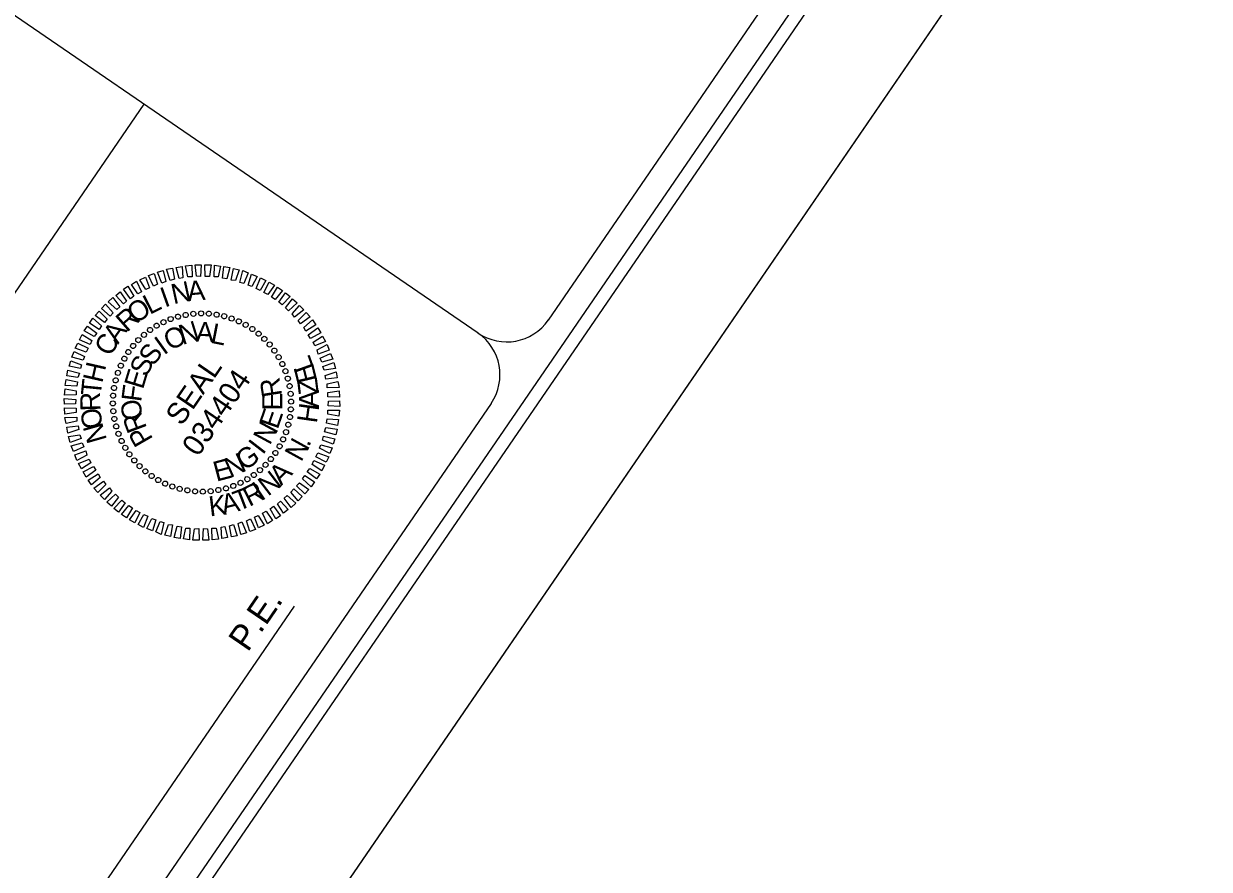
# Model space of a CAD drawing. Extents: x 2312641 to 2338852, y 590461 to 618614.
# Drawn here: x 2335572 to 2338852, y 606464 to 608804 of the extents above; entities that cross this region are included whole.
import ezdxf

# ---------------------------------------------------------------- set-up
doc = ezdxf.new("R2010")
doc.units = 0
for name, color, linetype in [('Exist Other Culture Sign Post Text', 7, 'Continuous'), ('Exist Property Iron Pin Cogo Number', 7, 'Continuous'), ('Exist Utilities Power Joint Use Telephone CELL', 7, 'Continuous'), ('Exist Utilities Power Joint Use Telephone Text', 7, 'Continuous'), ('Exist Vegetation Woods Line Text', 7, 'Continuous')]:
    doc.layers.add(name, color=color, linetype=linetype)

msp = doc.modelspace()

# ---------------------------------------------------------------- linework, layer by layer
at = {"layer": 'Exist Other Culture Sign Post Text'}
msp.add_line((2325524.4, 590461.2), (2338852.2, 609908.5), dxfattribs=at)
at = {"layer": 'Exist Property Iron Pin Cogo Number'}
for p, q in [((2336829.3, 607947.5), (2334981.6, 609213.7)), ((2334158.7, 606032.4), (2335905.2, 608580.8)), ((2335201.2, 605558.1), (2336321.2, 607192.1))]:
    msp.add_line(p, q, dxfattribs=at)
for points in [[(2326636.7, 592703), (2338350, 609794.5)], [(2337024, 607983.8), (2338252.5, 609776.4)], [(2335284.6, 605445.8), (2336865.7, 607752.9)]]:
    msp.add_lwpolyline(points, dxfattribs=at)
for centre, start, end in [((2336907.9, 608063.4), 235.5761, 325.5761), ((2336749.6, 607832.5), 325.5761, 55.5761)]:
    msp.add_arc(centre, 140, start, end, dxfattribs=at)
at = {"layer": 'Exist Utilities Power Joint Use Telephone CELL'}
msp.add_lwpolyline([(2326149.2, 618614.2), (2312821.5, 599166.9), (2325524.4, 590461.2), (2338852.2, 609908.5)], close=True, dxfattribs=at)
at = {"layer": 'Exist Utilities Power Joint Use Telephone Text'}
msp.add_lwpolyline([(2325368.2, 590788.9), (2338557.5, 610034.1), (2326372.9, 618384.6), (2313183.6, 599139.4)], close=True, dxfattribs=at)
at = {"layer": 'Exist Vegetation Woods Line Text'}
for p, q in [((2336041.2, 608001.7), (2336041.2, 608001.7)), ((2336062.4, 608002.5), (2336062.4, 608002.5)), ((2336084.2, 608001.6), (2336084.2, 608001.6)), ((2335939.5, 607968.1), (2335939.5, 607968.1)), ((2335958.3, 607978.7), (2335958.3, 607978.7)), ((2335978.3, 607986.7), (2335978.3, 607986.7)), ((2335998.9, 607993.7), (2335998.9, 607993.7)), ((2336019.6, 607998.3), (2336019.6, 607998.3)), ((2336105.6, 607999.3), (2336105.6, 607999.3)), ((2336126.3, 607995), (2336126.3, 607995)), ((2336146.8, 607988.5), (2336146.8, 607988.5)), ((2336167, 607979.9), (2336167, 607979.9)), ((2336186.3, 607970.7), (2336186.3, 607970.7)), ((2335904.2, 607943.1), (2335904.2, 607943.1)), ((2335921.3, 607956.5), (2335921.3, 607956.5)), ((2336204.6, 607959.2), (2336204.6, 607959.2)), ((2336221.9, 607946.1), (2336221.9, 607946.1)), ((2335874.6, 607912.5), (2335874.6, 607912.5)), ((2335889.1, 607928.3), (2335889.1, 607928.3)), ((2336237.6, 607931.6), (2336237.6, 607931.6)), ((2336252.4, 607916.5), (2336252.4, 607916.5)), ((2335849.9, 607877), (2335849.9, 607877)), ((2335861.5, 607895.3), (2335861.5, 607895.3)), ((2336265.9, 607899.4), (2336265.9, 607899.4)), ((2336277.4, 607881.1), (2336277.4, 607881.1)), ((2335832.1, 607837.5), (2335832.1, 607837.5)), ((2335840.8, 607857.7), (2335840.8, 607857.7)), ((2336288, 607862.4), (2336288, 607862.4)), ((2336296, 607842.4), (2336296, 607842.4)), ((2335825.7, 607817), (2335825.7, 607817)), ((2336303, 607821.8), (2336303, 607821.8)), ((2335819.1, 607774.8), (2335819.1, 607774.8)), ((2335821.4, 607796.3), (2335821.4, 607796.3)), ((2336307.6, 607801.1), (2336307.6, 607801.1)), ((2336311, 607779.4), (2336311, 607779.4)), ((2335818.2, 607753), (2335818.2, 607753)), ((2336311.8, 607758.3), (2336311.8, 607758.3)), ((2335819, 607731.9), (2335819, 607731.9)), ((2335822.4, 607710.2), (2335822.4, 607710.2)), ((2336308.6, 607715.1), (2336308.6, 607715.1)), ((2336310.9, 607736.5), (2336310.9, 607736.5)), ((2335827, 607689.5), (2335827, 607689.5)), ((2336297.9, 607673.8), (2336297.9, 607673.8)), ((2336304.3, 607694.3), (2336304.3, 607694.3)), ((2335834, 607669), (2335834, 607669)), ((2335842, 607649), (2335842, 607649)), ((2336289.2, 607653.6), (2336289.2, 607653.6)), ((2335852.6, 607630.2), (2335852.6, 607630.2)), ((2335864.1, 607612), (2335864.1, 607612)), ((2336268.5, 607616), (2336268.5, 607616)), ((2336280.1, 607634.4), (2336280.1, 607634.4)), ((2335877.6, 607594.9), (2335877.6, 607594.9)), ((2335892.4, 607579.8), (2335892.4, 607579.8)), ((2336240.9, 607583), (2336240.9, 607583)), ((2336255.4, 607598.8), (2336255.4, 607598.8)), ((2335908.1, 607565.3), (2335908.1, 607565.3)), ((2335925.4, 607552.1), (2335925.4, 607552.1)), ((2335943.7, 607540.6), (2335943.7, 607540.6)), ((2336190.5, 607543.3), (2336190.5, 607543.3)), ((2336208.7, 607554.8), (2336208.7, 607554.8)), ((2336225.8, 607568.2), (2336225.8, 607568.2)), ((2335963, 607531.4), (2335963, 607531.4)), ((2335983.2, 607522.8), (2335983.2, 607522.8)), ((2336003.7, 607516.4), (2336003.7, 607516.4)), ((2336024.4, 607512.1), (2336024.4, 607512.1)), ((2336045.8, 607509.7), (2336045.8, 607509.7)), ((2336067.7, 607508.9), (2336067.7, 607508.9)), ((2336088.8, 607509.7), (2336088.8, 607509.7)), ((2336110.4, 607513), (2336110.4, 607513)), ((2336131.1, 607517.6), (2336131.1, 607517.6)), ((2336151.7, 607524.7), (2336151.7, 607524.7)), ((2336171.7, 607532.7), (2336171.7, 607532.7))]:
    msp.add_line(p, q, dxfattribs=at)
for points in [[(2336001.5, 608098.6), (2335993.9, 608129), (2336010.2, 608132.3), (2336012.1, 608100.4)], [(2336025.8, 608103.2), (2336019.7, 608134.3), (2336036.5, 608135.6), (2336037.8, 608103.5)], [(2336049.9, 608104.9), (2336045.9, 608136.4), (2336063, 608136.4), (2336060.9, 608104.7)], [(2336073.7, 608104.5), (2336072.5, 608136.5), (2336090, 608136.2), (2336085.7, 608104.8)], [(2336098.8, 608103.3), (2336099.6, 608135.7), (2336115.9, 608132.7), (2336109.9, 608103)], [(2336121.9, 608099.8), (2336125.6, 608132.2), (2336142.2, 608128.8), (2336133.6, 608098)], [(2335909.3, 608068.7), (2335893.3, 608095.2), (2335908.4, 608102.9), (2335919.4, 608073.2)], [(2335931, 608077.4), (2335916.6, 608107.5), (2335932.3, 608112.4), (2335941.9, 608083.2)], [(2335954.4, 608086.1), (2335941.8, 608116.2), (2335957.9, 608120.9), (2335965.3, 608090.1)], [(2335977.4, 608093.3), (2335967.2, 608124.2), (2335983.5, 608127.5), (2335988.7, 608097)], [(2336146.1, 608094.5), (2336151.9, 608126.6), (2336167.6, 608122.7), (2336157.4, 608092.9)], [(2336170.1, 608088), (2336178, 608120.5), (2336193.1, 608114.1), (2336180.6, 608085.2)], [(2336193, 608080), (2336202.3, 608111), (2336217.9, 608104.2), (2336203.3, 608076.7)], [(2336215.2, 608070.7), (2336227, 608101.1), (2336241.8, 608093.2), (2336226.1, 608065.8)], [(2335867.5, 608042.7), (2335847.8, 608069.2), (2335860.3, 608077.5), (2335876.6, 608050.3)], [(2335887.4, 608056.1), (2335870, 608082.3), (2335884.1, 608091.2), (2335897.9, 608062.1)], [(2336236.5, 608060.1), (2336250.8, 608089), (2336265.3, 608080.6), (2336246.9, 608054.4)], [(2336257.3, 608047), (2336273.6, 608074.5), (2336287.6, 608065.3), (2336267.1, 608040.5)], [(2335829.5, 608013), (2335805.6, 608034.7), (2335818.1, 608046.5), (2335837.3, 608020.2)], [(2335847.9, 608029.1), (2335826.5, 608052.1), (2335839, 608062.1), (2335856.4, 608035.9)], [(2336277.5, 608033), (2336295.9, 608059.2), (2336308.9, 608049.4), (2336286.8, 608025.7)], [(2336295.9, 608018), (2336315.7, 608042.6), (2336328.5, 608031.8), (2336304.4, 608009.4)], [(2335794.9, 607977.5), (2335769.4, 607996.7), (2335780.8, 608008.6), (2335803.1, 607986.3)], [(2335811.2, 607995), (2335787.4, 608016), (2335798.4, 608028.2), (2335819, 608004.1)], [(2336314.6, 608000.9), (2336334.7, 608024.2), (2336346.7, 608012.1), (2336321.1, 607991.9)], [(2336330.8, 607982.6), (2336352.9, 608004.5), (2336364.6, 607992.7), (2336337.2, 607973.6)], [(2335766.8, 607938.4), (2335738.7, 607953.9), (2335748.1, 607967.2), (2335773.7, 607947.9)], [(2335780.2, 607957.8), (2335753.5, 607975.4), (2335762.8, 607988.7), (2335787.1, 607967.4)], [(2336346.4, 607963.4), (2336370.6, 607984), (2336379.8, 607970.3), (2336352.1, 607953.2)], [(2335755.3, 607916.5), (2335726, 607929.3), (2335733.6, 607944.3), (2335760.5, 607927.2)], [(2336359.1, 607943.3), (2336385.3, 607962.5), (2336394, 607948), (2336365.4, 607933.2)], [(2336372.5, 607922.6), (2336398.2, 607939.3), (2336406.9, 607924.7), (2336377.1, 607912.6)], [(2335744.7, 607895.2), (2335714.1, 607905.9), (2335721.8, 607920.3), (2335750, 607905.8)], [(2336383.7, 607901.1), (2336411.1, 607916), (2336417.2, 607900.2), (2336386.7, 607889.7)], [(2335728.6, 607849.3), (2335697.7, 607856.1), (2335702.4, 607871.2), (2335731.4, 607859.8)], [(2335736.2, 607872.5), (2335704.7, 607880.9), (2335711.1, 607896.8), (2335739.9, 607882.5)], [(2336392, 607878), (2336420.5, 607890.9), (2336427.3, 607875.3), (2336396.2, 607867.5)], [(2335721.9, 607824.8), (2335691, 607829.9), (2335694.2, 607845.4), (2335726.2, 607836.7)], [(2336399.4, 607855.4), (2336429.5, 607866.2), (2336434.2, 607850.1), (2336403, 607844.8)], [(2336405.5, 607830.7), (2336436.2, 607840.6), (2336438.8, 607824.1), (2336407.8, 607819.9)], [(2335718.6, 607801.1), (2335686.9, 607803.1), (2335689.6, 607819.6), (2335720.8, 607812.6)], [(2336411, 607807.7), (2336440.9, 607813.9), (2336444.3, 607797.5), (2336411.6, 607796.1)], [(2335716.8, 607777), (2335684.6, 607776.4), (2335686.4, 607793.5), (2335717, 607788)], [(2336412.9, 607782.9), (2336444.2, 607787.6), (2336445.5, 607770.8), (2336413, 607771.6)], [(2335715.1, 607752.1), (2335684.2, 607750.8), (2335683.4, 607766.6), (2335716.2, 607764.4)], [(2335717.2, 607728.4), (2335685.8, 607723.8), (2335684.5, 607740.5), (2335717, 607739.7)], [(2336414.9, 607759.2), (2336445.8, 607760.6), (2336446.6, 607744.8), (2336413.8, 607746.9)], [(2335719, 607703.6), (2335689.1, 607697.5), (2335685.7, 607713.8), (2335718.4, 607715.2)], [(2336411.4, 607710.2), (2336443.1, 607708.2), (2336440.4, 607691.7), (2336409.2, 607698.8)], [(2336413.2, 607734.4), (2336445.4, 607734.9), (2336443.6, 607717.9), (2336413, 607723.3)], [(2335724.5, 607680.6), (2335693.8, 607670.8), (2335691.2, 607687.3), (2335722.2, 607691.5)], [(2336408.1, 607686.5), (2336439, 607681.5), (2336435.8, 607665.9), (2336403.8, 607674.6)], [(2335730.6, 607655.9), (2335700.5, 607645.2), (2335695.8, 607661.2), (2335727, 607666.6)], [(2335738, 607633.3), (2335709.5, 607620.4), (2335702.7, 607636), (2335733.8, 607643.8)], [(2336401.4, 607662.1), (2336432.3, 607655.2), (2336427.6, 607640.1), (2336398.6, 607651.5)], [(2335746.3, 607610.2), (2335718.9, 607595.3), (2335712.8, 607611.1), (2335743.3, 607621.6)], [(2336385.3, 607616.2), (2336415.9, 607605.4), (2336408.2, 607591), (2336380, 607605.5)], [(2336393.8, 607638.8), (2336425.3, 607630.4), (2336419, 607614.6), (2336390.1, 607628.9)], [(2335757.5, 607588.7), (2335731.8, 607572.1), (2335723.1, 607586.6), (2335752.9, 607598.8)], [(2335770.9, 607568), (2335744.7, 607548.8), (2335736.1, 607563.4), (2335764.6, 607578.1)], [(2336374.7, 607594.8), (2336404, 607582), (2336396.4, 607567), (2336369.5, 607584.2)], [(2335783.6, 607547.9), (2335759.4, 607527.4), (2335750.2, 607541.1), (2335777.9, 607558.1)], [(2336349.8, 607553.5), (2336376.5, 607535.9), (2336367.2, 607522.7), (2336342.9, 607544)], [(2336363.2, 607573), (2336391.3, 607557.4), (2336381.9, 607544.2), (2336356.3, 607563.4)], [(2335799.2, 607528.8), (2335777.1, 607506.8), (2335765.4, 607518.7), (2335792.8, 607537.7)], [(2335815.4, 607510.4), (2335795.3, 607487.2), (2335783.3, 607499.2), (2335808.9, 607519.4)], [(2336318.8, 607516.3), (2336342.6, 607495.3), (2336331.6, 607483.1), (2336311.1, 607507.3)], [(2336335.1, 607533.8), (2336360.6, 607514.6), (2336349.2, 607502.7), (2336326.9, 607525.1)], [(2335834.1, 607493.3), (2335814.4, 607468.7), (2335801.5, 607479.6), (2335825.6, 607501.9)], [(2335852.5, 607478.3), (2335834.1, 607452.2), (2335821.1, 607461.9), (2335843.2, 607485.6)], [(2336282.1, 607482.2), (2336303.5, 607459.2), (2336291, 607449.2), (2336273.6, 607475.5)], [(2336300.5, 607498.4), (2336324.4, 607476.7), (2336311.9, 607464.9), (2336292.7, 607491.1)], [(2335872.7, 607464.3), (2335856.4, 607436.9), (2335842.4, 607446.1), (2335862.9, 607470.8)], [(2335893.5, 607451.2), (2335879.2, 607422.4), (2335864.7, 607430.8), (2335883.1, 607456.9)], [(2335914.8, 607440.7), (2335903, 607410.2), (2335888.2, 607418.2), (2335903.9, 607445.5)], [(2336220.7, 607442.6), (2336236.8, 607416.1), (2336221.6, 607408.4), (2336210.6, 607438.1)], [(2336242.6, 607455.3), (2336260, 607429.1), (2336245.9, 607420.1), (2336232.1, 607449.2)], [(2336262.5, 607468.6), (2336282.2, 607442.1), (2336269.7, 607433.9), (2336253.4, 607461.1)], [(2335937, 607431.4), (2335927.7, 607400.4), (2335912.1, 607407.1), (2335926.7, 607434.6)], [(2335959.9, 607423.3), (2335952, 607390.8), (2335936.9, 607397.3), (2335949.4, 607426.1)], [(2335983.9, 607416.9), (2335978.1, 607384.8), (2335962.4, 607388.7), (2335972.6, 607418.4)], [(2336008.1, 607411.5), (2336004.4, 607379.2), (2335987.8, 607382.5), (2335996.4, 607413.4)], [(2336128.5, 607412.8), (2336136.1, 607382.4), (2336119.8, 607379), (2336117.9, 607410.9)], [(2336152.6, 607418.1), (2336162.8, 607387.1), (2336146.5, 607383.8), (2336141.3, 607414.3)], [(2336175.6, 607425.2), (2336188.2, 607395.2), (2336172.1, 607390.5), (2336164.7, 607421.2)], [(2336199, 607433.9), (2336213.4, 607403.9), (2336197.7, 607398.9), (2336188.2, 607428.2)], [(2336031.2, 607408.1), (2336030.4, 607375.6), (2336014.1, 607378.7), (2336020.1, 607408.3)], [(2336056.3, 607406.8), (2336057.5, 607374.8), (2336040, 607375.1), (2336044.3, 607406.5)], [(2336080.1, 607406.4), (2336084.1, 607374.9), (2336067, 607375), (2336069.1, 607406.6)], [(2336104.2, 607408.1), (2336110.3, 607377.1), (2336093.5, 607375.8), (2336092.3, 607407.8)]]:
    msp.add_lwpolyline(points, close=True, dxfattribs=at)
for centre, major_axis in [((2335998.8, 607993.2), (-1.9, 6.82)), ((2336019.7, 607998.1), (-1.3, 6.96)), ((2336041, 608001.1), (-0.69, 7.05)), ((2336062.5, 608002.3), (-0.07, 7.08)), ((2336084, 608001.5), (0.55, 7.06)), ((2336105.4, 607998.9), (1.16, 6.98)), ((2336126.4, 607994.5), (1.76, 6.86)), ((2335939.6, 607968), (-3.6, 6.1)), ((2335958.5, 607978.1), (-3.06, 6.39)), ((2335978.3, 607986.5), (-2.49, 6.63)), ((2336147, 607988.2), (2.35, 6.68)), ((2336167, 607980.2), (2.93, 6.45)), ((2336186.1, 607970.5), (3.48, 6.17)), ((2336204.4, 607959.1), (4, 5.84)), ((2335888.9, 607928.3), (-5.06, 4.96)), ((2335904.6, 607943), (-4.6, 5.38)), ((2335921.5, 607956.2), (-4.12, 5.76)), ((2336221.6, 607946.2), (4.5, 5.47)), ((2336237.6, 607931.8), (4.96, 5.06)), ((2335861.6, 607895.1), (-5.84, 4)), ((2335874.5, 607912.3), (-5.47, 4.5)), ((2336252.3, 607916.1), (5.38, 4.6)), ((2336265.6, 607899.1), (5.76, 4.12)), ((2335850.2, 607876.8), (-6.17, 3.48)), ((2336277.3, 607881.1), (6.1, 3.6)), ((2336287.4, 607862.1), (6.39, 3.06)), ((2335832.4, 607837.7), (-6.68, 2.35)), ((2335840.5, 607857.6), (-6.45, 2.93)), ((2336295.9, 607842.3), (6.63, 2.49)), ((2335821.7, 607796), (-6.98, 1.16)), ((2335826.2, 607817.1), (-6.86, 1.76)), ((2336302.5, 607821.9), (6.82, 1.9)), ((2336307.4, 607800.9), (6.96, 1.3)), ((2335819.1, 607774.7), (-7.06, 0.55)), ((2336310.4, 607779.6), (7.05, 0.69)), ((2335818.4, 607753.2), (-7.08, -0.07)), ((2335819.6, 607731.7), (-7.05, -0.69)), ((2336310.9, 607736.6), (7.06, -0.55)), ((2336311.6, 607758.1), (7.08, 0.07)), ((2335822.6, 607710.4), (-6.96, -1.3)), ((2336308.3, 607715.3), (6.98, -1.16)), ((2335827.5, 607689.5), (-6.82, -1.9)), ((2335834.1, 607669), (-6.63, -2.49)), ((2336297.6, 607673.7), (6.68, -2.35)), ((2336303.8, 607694.2), (6.86, -1.76)), ((2335842.6, 607649.2), (-6.39, -3.06)), ((2336279.8, 607634.5), (6.17, -3.48)), ((2336289.5, 607653.7), (6.45, -2.93)), ((2335852.7, 607630.2), (-6.1, -3.6)), ((2335864.4, 607612.2), (-5.76, -4.12)), ((2336255.5, 607599.1), (5.47, -4.5)), ((2336268.4, 607616.3), (5.84, -4)), ((2335877.7, 607595.3), (-5.38, -4.6)), ((2335892.4, 607579.6), (-4.96, -5.06)), ((2336225.4, 607568.4), (4.6, -5.38)), ((2336241.1, 607583.1), (5.06, -4.96)), ((2335908.4, 607565.2), (-4.5, -5.47)), ((2335925.6, 607552.3), (-4, -5.84)), ((2335943.9, 607540.9), (-3.48, -6.17)), ((2336171.5, 607533.2), (3.06, -6.39)), ((2336190.4, 607543.4), (3.6, -6.1)), ((2336208.5, 607555.1), (4.12, -5.76)), ((2335963, 607531.1), (-2.93, -6.45)), ((2335983, 607523.1), (-2.35, -6.68)), ((2336003.6, 607516.8), (-1.76, -6.86)), ((2336024.6, 607512.4), (-1.16, -6.98)), ((2336046, 607509.8), (-0.55, -7.06)), ((2336067.5, 607509.1), (0.07, -7.08)), ((2336089, 607510.2), (0.69, -7.05)), ((2336110.3, 607513.3), (1.3, -6.96)), ((2336131.2, 607518.1), (1.9, -6.82)), ((2336151.7, 607524.8), (2.49, -6.63))]:
    msp.add_ellipse(centre, major_axis=major_axis, ratio=0.999708, dxfattribs=at)

# ---------------------------------------------------------------- texts
at = {"layer": 'Exist Property Iron Pin Cogo Number'}
msp.add_text('P.E.', height=69.99, rotation=55.5761, dxfattribs=at).set_placement((2336191.7, 607062.8))
at = {"layer": 'Exist Vegetation Woods Line Text'}
for s, height, rotation, p in [('I', 55.4, 19.5962, (2335961.9, 608018.1)), ('N', 55.4, 12.395, (2335986.3, 608027.3)), ('A', 55.4, 5.1932, (2336026.5, 608035.6)), ('O', 55.4, 33.9972, (2335881.3, 607971.8)), ('L', 55.4, 26.797, (2335920.3, 607997.8)), ('R', 55.4, 41.1972, (2335857, 607948.3)), ('A', 55.4, 55.5964, (2335832.6, 607914.9)), ('N', 55.4, 17.0527, (2336010.8, 607914.5)), ('A', 55.4, 358.3363, (2336047.6, 607923.8)), ('L', 55.5, 348.9769, (2336086.5, 607921.2)), ('C', 55.4, 62.7959, (2335813.7, 607880.9)), ('I', 55.4, 35.7657, (2335959.7, 607885.3)), ('O', 55.4, 26.4096, (2335976.3, 607897.9)), ('S', 55.4, 54.4765, (2335930.6, 607853.8)), ('S', 55.4, 63.8317, (2335911.6, 607824)), ('L', 55.4, 109.8751, (2336375.9, 607851.2)), ('H', 55.4, 77.1956, (2335788.9, 607807.7)), ('E', 55.4, 73.1871, (2335901.5, 607790)), ('SEAL', 58.98, 55.5761, (2336008.9, 607688.5)), ('034404', 59, 55.5761, (2336054.3, 607603.2)), ('E', 55.4, 103.7004, (2336383.9, 607817.5)), ('T', 55.4, 84.3958, (2335784.9, 607772.1)), ('F', 55.4, 82.5431, (2335896.5, 607755.6)), ('R', 55.4, 99.0575, (2336287, 607775.2)), ('Z', 55.4, 97.1609, (2336388.4, 607781.2)), ('R', 55.4, 91.5966, (2335784.5, 607732.3)), ('E', 55.4, 89.7002, (2336287.1, 607733.4)), ('A', 55.4, 89.9112, (2336388.4, 607740.7)), ('O', 55.4, 98.7978, (2335791.2, 607687.2)), ('O', 55.4, 101.2573, (2335902.8, 607712.5)), ('E', 55.4, 70.9878, (2336274.4, 607679.3)), ('H', 55.4, 81.9512, (2336382.6, 607696.6)), ('R', 55.4, 110.6157, (2335913.4, 607684.9)), ('N', 55.4, 105.9996, (2335802.6, 607652.6)), ('P', 55.5, 119.975, (2335931, 607654.4)), ('N', 55.4, 61.6325, (2336252.5, 607635.5)), ('I', 55.4, 52.2773, (2336233.1, 607608.8)), ('N', 55.4, 61.1714, (2336339.5, 607589.2)), ('.', 55.4, 69.5921, (2336361.6, 607630.8)), ('N', 55.4, 24.21, (2336143, 607546.3)), ('G', 55.4, 33.5663, (2336182.1, 607565.3)), ('E', 55.4, 14.853, (2336104.6, 607536.3)), ('A', 55.4, 45.8274, (2336284.5, 607523.6)), ('N', 55.4, 37.4068, (2336247.5, 607494.5)), ('T', 55.4, 20.898, (2336164.5, 607454.6)), ('R', 55.4, 26.8808, (2336195.9, 607466.2)), ('I', 55.4, 33.2859, (2336227.9, 607482.3)), ('K', 55.4, 6.7441, (2336086.8, 607440.3)), ('A', 55.4, 13.6483, (2336125.1, 607444.9))]:
    msp.add_text(s, height=height, rotation=rotation, dxfattribs=at).set_placement(p)

doc.saveas('drawing.dxf')
